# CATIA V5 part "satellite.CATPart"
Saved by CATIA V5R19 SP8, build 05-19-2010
Part number: satellite
Bounding box of the stored display mesh (mm): x -22.5 to 22.5, y -22.5 to 22.5, z 0 to 200
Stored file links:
  G:\EU_thinkMotion\CFAO_2010\St2M_groupe2\St2M_groupe2\npeyre\npeyre\satellite.CATPart
  C:\Documents and Settings\Niels\Mes documents\IFMA\2A\Calculs et CFAO\Modélisation eolienne axe vertical\eolienne avec train reducteur\assemblage.CATProduct
  G:\EU_thinkMotion\CFAO_2010\St2M_groupe2\St2M_groupe2\npeyre\npeyre\pale.CATPart
  G:\EU_thinkMotion\CFAO_2010\St2M_groupe2\St2M_groupe2\npeyre\npeyre\alesage axe rotor.CATPart
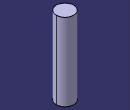
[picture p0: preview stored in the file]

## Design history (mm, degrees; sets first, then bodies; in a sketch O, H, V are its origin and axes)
Parameters
  `diametre satellite` = 45 mm
Set1
  DatumSurface1: linked copy from another document
  DatumSurface2: linked copy from another document
Body1 (main body)
  Sketch1 on xy-plane, origin (0, 0, 0), H (1, 0, 0), V (0, 1, 0)
    circle A1 centre (0, 0) radius 22.5
    point P1 (0, 0)
    radius A1 = 22.5 {= `diametre satellite` /2}
    coincidence: P1 O
  Pad1: profile Sketch1, direction (0, 0, 1), length 200
  Line1: stored without definition
Relations
  Pad1.FirstLimit.Length = 200mm (deactivated)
